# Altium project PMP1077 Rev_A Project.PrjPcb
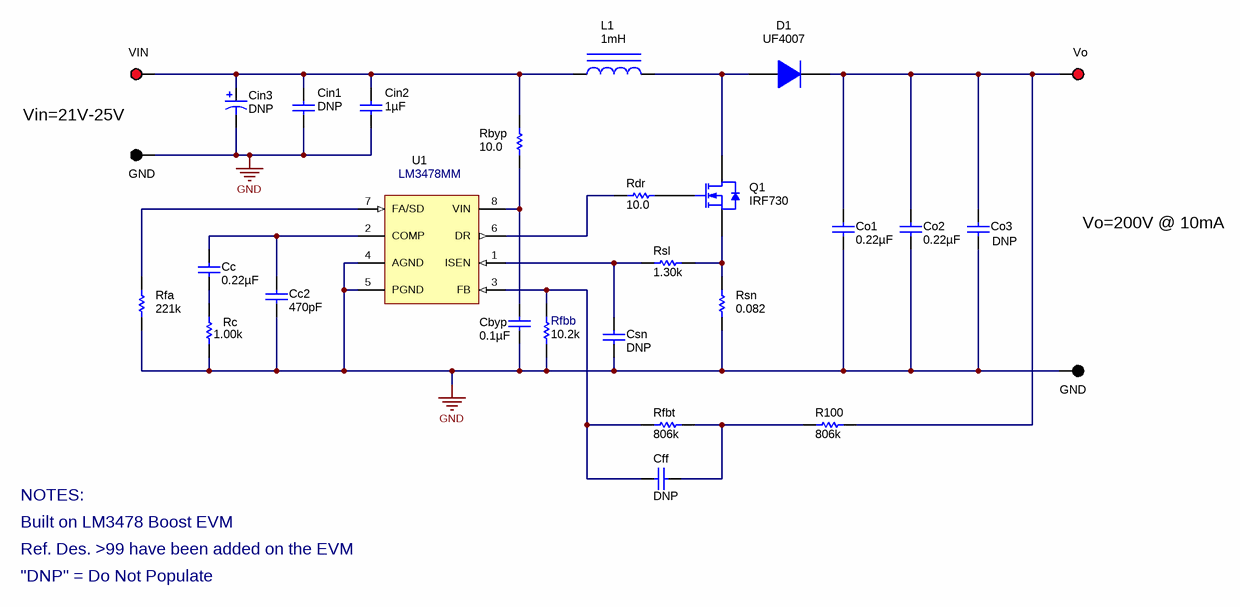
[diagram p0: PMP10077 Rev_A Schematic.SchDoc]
TechSupport: http://www.ti.com/support; SCH_Rev: A; PRJ_Title: 24Vin to 200Vout 10mA Boost; PRJ_Number: PMP10077; PRJ_Engineer: R. Scibilia; PRJ_Customer: Public Release; PCB_Rev: E1; PCB_Layout: Who did the Layout?; CopyrightYear: 2014
1 sheet, 28 parts. Net scope: global (net labels, ports and power ports of the same name join across sheets).

## Sheet PMP10077 Rev_A Schematic.SchDoc: 24Vin to 200Vout 10mA Boost
size A4; Date: Not shown in title block; ApprovedBy: Not shown in title block; CheckedBy: Not shown in title block; Author: Not shown in title block; CompanyName: Not shown in title block; DrawnBy: R. Scibilia; Engineer: Not shown in title block; Organization: Not shown in title block; Address1: Not shown in title block; Address2: Not shown in title block; Address3: Not shown in title block; Address4: Not shown in title block; DocumentNumber: 1; Revision: Use project parameter SCH_Rev; SheetNumber: 1; SheetTotal: 1; PageSetup: Record=PageOptions|CenterHorizontal=True|CenterVertical=True|PrintScale=1.00|XCorrection=1.00|YCorrection=1.00|PrintKind=0|BorderSize=5000000|LeftOffset=0|BottomOffset=0|Orientation=2|PaperLength=1000|PaperWidth=1000|Scale=100|PaperSource=15|PrintQuality=600|MediaType=1|DitherType=10|PaperKind=Letter|PrintScaleMode=1

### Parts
(Parts that share a designator on the sheet are numbered #1, #2 ... from top to bottom, then left to right.)
Cbyp  ValueDisplayed: 0.1µF  [0603]  (hidden comment: C1608X7R1H104K)
Cc  ValueDisplayed: 0.22µF  [0603]  (hidden comment: C1608X7R1C224K)
Cc2  ValueDisplayed: 470pF  [0603]  (hidden comment: C1608C0G1H471J)
Cff  DNP  [0603]
Cin1  DNP  [0603]
Cin2  ValueDisplayed: 1µF  [1206]  (hidden comment: C3216X7R1H105K)
Cin3  DNP  [CAPSMT_62_JC0]
Co1  ValueDisplayed: 0.22µF  [1210]  (hidden comment: GRM32DR72E224KW01L)
Co2  ValueDisplayed: 0.22µF  [1210]  (hidden comment: GRM32DR72E224KW01L)
Co3  DNP  [1210]
Csn  DNP  [0603]
D1  UF4007  [DO-41]
GND#1  5001  [Keystone5001]  (value not drawn)
GND#2  5001  [Keystone5001]  (value not drawn)
L1  value 1mH  [DO3316T]  (hidden comment: SDR1005-102KL)
Q1  IRF730  [TO-220AB]
R100  value 806k  [0805_HV]  (hidden comment: CRCW0805806KFKEA)
Rbyp  value 10.0  [0603]  (hidden comment: CRCW060310R0FKEA)
Rc  value 1.00k  [0603]  (hidden comment: CRCW06031K00FKEA)
Rdr  value 10.0  [0603]  (hidden comment: CRCW060310R0FKEA)
Rfa  value 221k  [0603]  (hidden comment: CRCW0603221KFKEA)
Rfbb  value 10.2k  [0603]  (hidden comment: CRCW060310K2FKEA)
Rfbt  value 806k  [0805_HV]  (hidden comment: CRCW0805806KFKEA)
Rsl  value 1.30k  [0603]  (hidden comment: CRCW06031K30FKEA)
Rsn  value 0.082  [1206]  (hidden comment: MCR18EZHFSR082)
U1  LM3478MM  [MUA08A_N]
VIN  5000  [Keystone5000]  (value not drawn)
Vo  5000  [Keystone5000]  (value not drawn)

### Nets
GND: Cbyp.2 Cc2.2 Cin1.2 Cin2.2 Cin3.2(-) Co1.2 Co2.2 Co3.2 Csn.2 GND#1.1 GND#2.1 Rc.1 Rfa.1 Rfbb.1 Rsn.1 U1.4(AGND) U1.5(PGND)
NetCbyp_1: Cbyp.1 Rbyp.1 U1.8(VIN)
NetCc_1: Cc.1 Cc2.1 U1.2(COMP)
NetCc_2: Cc.2 Rc.2
NetCff_1: Cff.1 Rfbb.2 Rfbt.1 U1.3(FB)
NetCff_2: Cff.2 R100.1 Rfbt.2
NetCin1_1: Cin1.1 Cin2.1 Cin3.1(+) L1.1 Rbyp.2 VIN.1
NetCo1_1: Co1.1 Co2.1 Co3.1 D1.1(K) R100.2 Vo.1
NetCsn_1: Csn.1 Rsl.1 U1.1(ISEN)
NetD1_2: D1.2(A) L1.2 Q1.2(D)
NetQ1_1: Q1.1(G) Rdr.1
NetQ1_3: Q1.3(S) Rsl.2 Rsn.2
NetRdr_2: Rdr.2 U1.6(DR)
NetRfa_2: Rfa.2 U1.7(FA/SD)

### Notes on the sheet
- Vin=21V-25V
- Vo=200V @ 10mA
- NOTES:
- Built on LM3478 Boost EVM
- Ref. Des. >99 have been added on the EVM
- "DNP" = Do Not Populate

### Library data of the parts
Cbyp = C1608X7R1H104K: CAP, CERM, 0.1uF, 50V, +/-10%, X7R, 0603; Manufacturer: TDK; Polarized: N; CompType: Capacitor; U/M: EA; Cap_F: 0.0000001; Tolerance_%: 10; ESR_Ohm: 0.017; Value1: 0.017 ohm; VDC_V: 50; TaMin_C: -55; TaMax_C: 125
Cc = C1608X7R1C224K: CAP, CERM, 0.22uF, 16V, +/-10%, X7R, 0603; Manufacturer: TDK; Polarized: N; CompType: Capacitor; U/M: EA; Cap_F: 0.00000022; Tolerance_%: 10; ESR_Ohm: 0.0125; Value1: 0.0125 ohm; VDC_V: 16; TaMin_C: -55; TaMax_C: 125
Cc2 = C1608C0G1H471J: CAP, CERM, 470pF, 50V, +/-5%, C0G/NP0, 0603; Manufacturer: TDK; Polarized: N; CompType: Capacitor; U/M: EA; Cap_F: 0.00000000047; Tolerance_%: 5; ESR_Ohm: 0.0922; Value1: 0.0922 ohm; VDC_V: 50; TaMin_C: -55; TaMax_C: 125
Cff Csn = C1608C0G1H471J: Polarized: N; CompType: Capacitor; Value: 470pF; U/M: EA; Cap_F: 0.00000000047; Tolerance_%: 5; ESR_Ohm: 0.0922; Value1: 0.0922 ohm; VDC_V: 50; Value2: 50V; TempCo: C0G/NP0; TaMin_C: -55; TaMax_C: 125
Cin1 = GRM188R60J105KA01D: Polarized: N; CompType: Capacitor; Value: 1uF; U/M: EA; Cap_F: 0.000001; Tolerance_%: 10; Value1: Unknown; VDC_V: 6.3; Value2: 6.3V; TempCo: X5R; TaMin_C: -55; TaMax_C: 85
Cin2 = C3216X7R1H105K: CAP, CERM, 1uF, 50V, +/-10%, X7R, 1206; Manufacturer: TDK; Polarized: N; CompType: Capacitor; U/M: EA; Cap_F: 0.000001; Tolerance_%: 10; ESR_Ohm: 0.01; Value1: 0.01 ohm; VDC_V: 50; IRMS_A: 3.2; TaMin_C: -55; TaMax_C: 125
Cin3 = APXA100ARA471MJC0G: Polarized: Y; CompType: Capacitor; Value: 470uF; U/M: EA; Cap_F: 0.00047; Tolerance_%: 20; Value1: 0.012 ohm; VDC_V: 10; Value2: 10V; ESR_Ohm: 0.012; IRMS_A: 5.3; TaMin_C: -55; TaMax_C: 105; Cap_Case: JC0
Co1 Co2 = GRM32DR72E224KW01L: CAP, CERM, 0.22uF, 250V, +/-10%, X7R, 1210; Manufacturer: MuRata; Polarized: N; CompType: Capacitor; U/M: EA; Cap_F: 0.00000022; Tolerance_%: 10; Value1: Unknown; VDC_V: 250; TaMin_C: -55; TaMax_C: 125
Co3 = GRM32DR72E224KW01L: CAP, CERM, 0.22uF, 250V, +/-10%, X7R, 1210; Polarized: N; CompType: Capacitor; ValueDisplayed: 0.22µF; U/M: EA; Cap_F: 0.00000022; Tolerance_%: 10; Value1: Unknown; VDC_V: 250; TaMin_C: -55; TaMax_C: 125
D1 = 1N4007: Diode, Fast Rectifier, 1000V, 1A, TH; Manufacturer: Fairchild Semiconductor; U/M: EA; Vf_V: 1.1; Value2: 1.1V; Io_A: 1; Vr_V: 1000; TJmax_C: 175; RJC_CperW: 50; Type: P-N
GND#1 GND#2 = 5001: Test Point, Miniature, Black, TH; Manufacturer: Keystone; CompType: Test Point Loop; U/M: EA
L1 = DO3316T-472MLB: Inductor, Drum Core, Ferrite, 1000uH, 0.35A, 3.9 ohm, SMD; Manufacturer: Bourns; Imax_A: 0.35; Irms: 0.3A @ 40C rise; Isat: 0.35A @ 10% inductance drop; DCR_ohm: 3.9; Value1: 3.9 ohm
Q1 = IRFB4410ZPBF: MOSFET, N-CH, 400V, 5.5A, TO-220AB; Manufacturer: Vishay; Alternate Manufacturer: None; U/M: EA; ChType: N; VdsMax_V: 100; Value1: 101 ohm; Rdson45_Ohm: 101; Value2: 83 nC; QgTyp_nC: 83; Vgs_V: 20; IdsMax_A: 97
R100 Rfbt = CRCW0805806KFKEA: RES, 806k ohm, 1%, 0.125W, 0805; Manufacturer: Vishay-Dale; CompType: Resistor; Res_ohm: 806000; Tolerance_%: 1; Power_W: 0.125; VDC_V: 150; TempCo: 100 ppm/C; EIA_Code: E96; U/M: EA
Rbyp Rdr = CRCW060310R0FKEA: RES, 10.0 ohm, 1%, 0.1W, 0603; Manufacturer: Vishay-Dale; CompType: Resistor; Res_ohm: 10; Value_Code: 10R0; Tolerance_%: 1; Power_W: 0.1; VDC_V: 75; TempCo: 100 ppm/C; EIA_Code: E96; U/M: EA
Rc = CRCW06031K00FKEA: RES, 1.00k ohm, 1%, 0.1W, 0603; Manufacturer: Vishay-Dale; CompType: Resistor; Res_ohm: 1000; Value_Code: 1k00; Tolerance_%: 1; Power_W: 0.1; VDC_V: 75; TempCo: 100 ppm/C; EIA_Code: E96; U/M: EA
Rfa = CRCW0603221KFKEA: RES, 221k ohm, 1%, 0.1W, 0603; Manufacturer: Vishay-Dale; CompType: Resistor; Res_ohm: 221000; Tolerance_%: 1; Power_W: 0.1; VDC_V: 75; TempCo: 100 ppm/C; EIA_Code: E96; U/M: EA
Rfbb = CRCW060310K2FKEA: RES, 10.2k ohm, 1%, 0.1W, 0603; Manufacturer: Vishay-Dale; CompType: Resistor; Res_ohm: 10200; Value_Code: 10k2; Tolerance_%: 1; Power_W: 0.1; VDC_V: 75; TempCo: 100 ppm/C; EIA_Code: E96; U/M: EA
Rsl = CRCW06031K30FKEA: RES, 1.30k ohm, 1%, 0.1W, 0603; Manufacturer: Vishay-Dale; CompType: Resistor; Res_ohm: 1300; Value_Code: 1k30; Tolerance_%: 1; Power_W: 0.1; VDC_V: 75; TempCo: 100 ppm/C; EIA_Code: E96; U/M: EA
Rsn = MCR18EZHFSR082: RES, 0.082 ohm, 1%, 0.25W, 1206; Manufacturer: Rohm; CompType: Resistor; Value_Code: R082; Tolerance_%: 1; Power_W: 0.25; VDC_V: 1.51; TempCo: 500 ppm/C; U/M: EA
U1 = LM3478MM: High Efficiency Low-Side N-Channel Controller for Switching Regulator, 8-pin MSOP; Manufacturer: Texas Instruments; PackageTopMarking: ZXTT*S14B; PowerWise: N; CompType: MiscPower
VIN Vo = 5000: Test Point, TH, Miniature, Red; Manufacturer: Keystone; CompType: Test Point Loop; U/M: EA

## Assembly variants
001: not fitted FID1 FID2 FID3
